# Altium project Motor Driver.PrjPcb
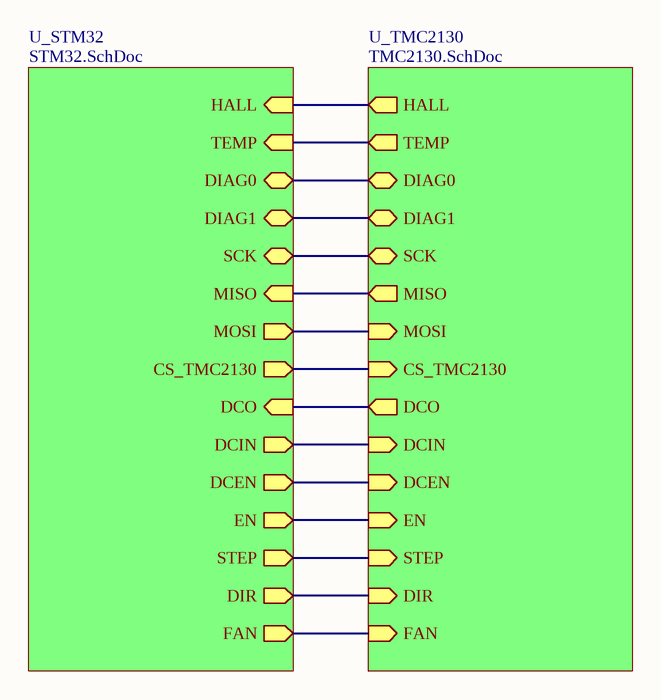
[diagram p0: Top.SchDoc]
3 sheets, 58 parts. Net scope: hierarchical (ports join the sheet entries above them; power ports are global).
Board file: PCB1.PcbDoc
Sheets:
  Top.SchDoc
    U_STM32 = STM32.SchDoc
    U_TMC2130 = TMC2130.SchDoc

## Sheet Top.SchDoc
size A

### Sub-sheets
U_STM32 = STM32.SchDoc: CS_TMC2130 (out), DIR (out), MISO (in), MOSI (out), SCK (bidir), EN (out), DIAG0 (bidir), HALL (in), DCO (in), DCEN (out), TEMP (in), DIAG1 (bidir), DCIN (out), STEP (out), FAN (out)
U_TMC2130 = TMC2130.SchDoc: DIAG1 (bidir), DIAG0 (bidir), DCO (out), DCIN (in), TEMP (out), HALL (out), DCEN (in), MOSI (in), SCK (bidir), MISO (out), STEP (in), DIR (in), EN (in), CS_TMC2130 (in), FAN (in)

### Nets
NetQ1_1: sheet U_STM32/FAN, sheet U_TMC2130/FAN
NetR2_2: sheet U_STM32/TEMP, sheet U_TMC2130/TEMP
NetU1_10: sheet U_STM32/CS_TMC2130, sheet U_TMC2130/CS_TMC2130
NetU1_11: sheet U_STM32/HALL, sheet U_TMC2130/HALL
NetU1_12: sheet U_STM32/EN, sheet U_TMC2130/EN
NetU1_13: sheet U_STM32/STEP, sheet U_TMC2130/STEP
NetU1_14: sheet U_STM32/DIR, sheet U_TMC2130/DIR
NetU1_15: sheet U_STM32/SCK, sheet U_TMC2130/SCK
NetU1_16: sheet U_STM32/MISO, sheet U_TMC2130/MISO
NetU1_17: sheet U_STM32/MOSI, sheet U_TMC2130/MOSI
NetU1_26: sheet U_STM32/DCO, sheet U_TMC2130/DCO
NetU1_27: sheet U_STM32/DCEN, sheet U_TMC2130/DCEN
NetU1_28: sheet U_STM32/DCIN, sheet U_TMC2130/DCIN
NetU1_45: sheet U_STM32/DIAG0, sheet U_TMC2130/DIAG0
NetU1_46: sheet U_STM32/DIAG1, sheet U_TMC2130/DIAG1

## Sheet STM32.SchDoc: Microcontroller & Communication
size A; Author: Luka & Emile; DrawnBy: Luka & Emile; Revision: 0.1; SheetNumber: 1; SheetTotal: 2
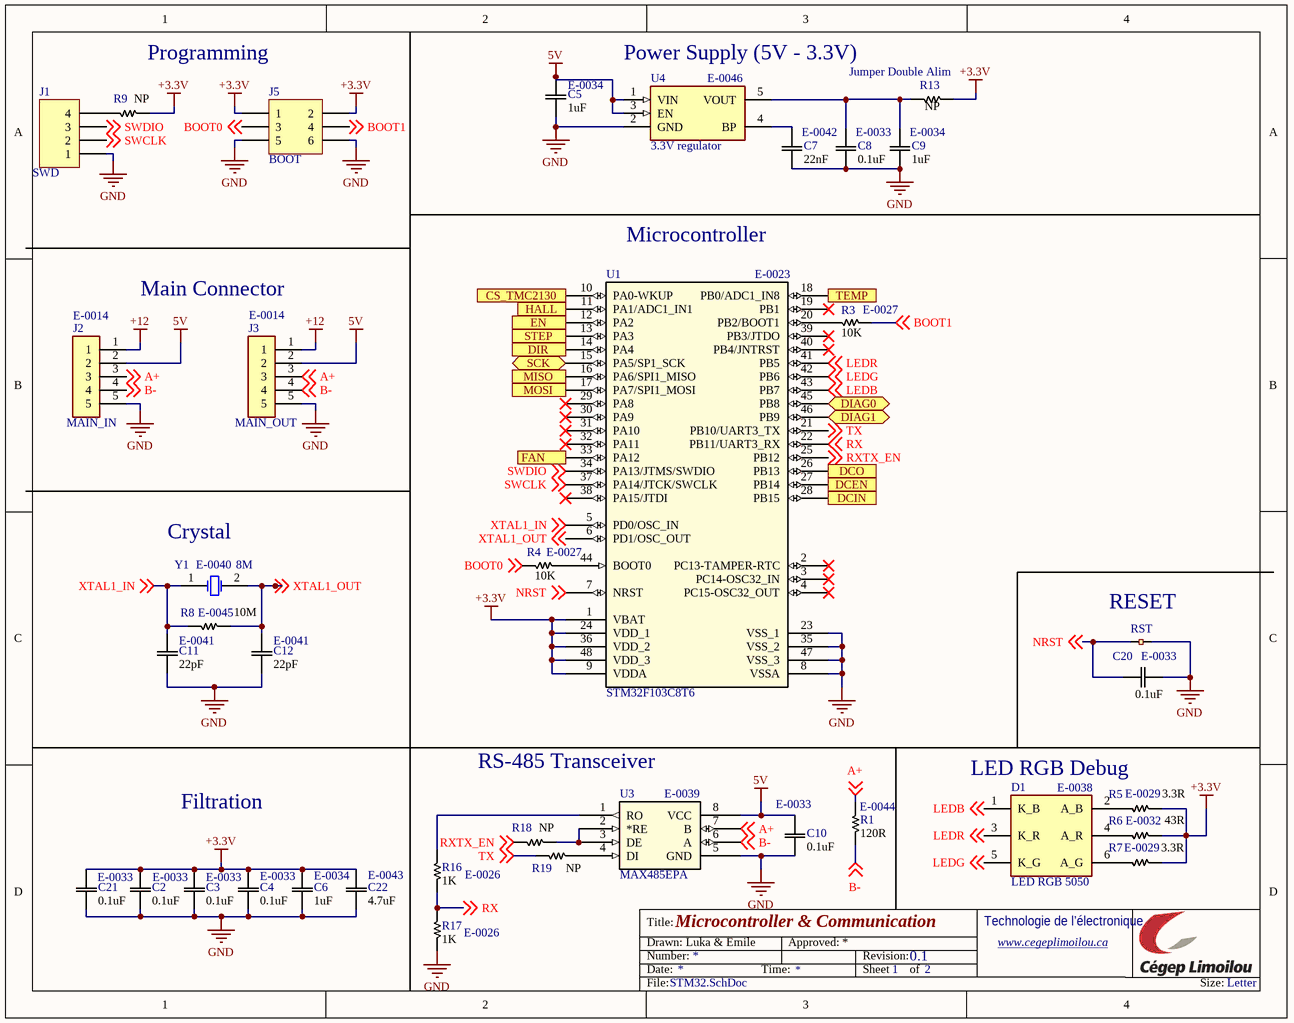
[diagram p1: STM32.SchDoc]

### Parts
C2  value 0.1uF  [0603]  (hidden comment: E-0033)
C3  value 0.1uF  [0603]  (hidden comment: E-0033)
C4  value 0.1uF  [0603]  (hidden comment: E-0033)
C5  value 1uF  [0603]  (hidden comment: E-0034)
C6  value 1uF  [0603]  (hidden comment: E-0034)
C7  value 22nF  [0603]  (hidden comment: E-0042)
C8  value 0.1uF  [0603]  (hidden comment: E-0033)
C9  value 1uF  [0603]  (hidden comment: E-0034)
C10  value 0.1uF  [0603]  (hidden comment: E-0033)
C11  value 22pF  [0603]  (hidden comment: E-0041)
C12  value 22pF  [0603]  (hidden comment: E-0041)
C20  value 0.1uF  [0603]  (hidden comment: E-0033)
C21  value 0.1uF  [0603]  (hidden comment: E-0033)
C22  value 4.7uF  [0603]  (hidden comment: E-0043)
D1  LED RGB 5050  [LED 5050]
J1  SWD  [HDR1X4]
J2  MAIN_IN  [JST 5POS 2.5mm 90°]
J3  MAIN_OUT  [JST 5POS 2.5mm 90°]
J5  BOOT  [Header 3x2 1.27mm SMD]
R1  value 120R  [0603]  (hidden comment: E-0044)
R3  value 10K  [0603]  (hidden comment: E-0027)
R4  value 10K  [0603]  (hidden comment: Resistor 0603)
R5  value 3.3R  [0603]  (hidden comment: E-0029)
R6  value 43R  [0603]  (hidden comment: E-0032)
R7  value 3.3R  [0603]  (hidden comment: E-0029)
R8  value 10M  [0603]  (hidden comment: E-0045)
R9  value NP  [0603]  (hidden comment: Jumper)
R13  value NP  [0603]  (hidden comment: Jumper)
R16  value 1K  [0603]  (hidden comment: E-0026)
R17  value 1K  [0603]  (hidden comment: E-0026)
R18  value NP  [0603]  (hidden comment: Jumper)
R19  value NP  [0603]  (hidden comment: Jumper)
RST  (no value)  [PAD]
U1  STM32F103C8T6  [LQFP-48]
U3  MAX485EPA  [DIP 8 - 3D]
U4  3.3V regulator  [SOT94P279X130-5N]
Y1  8M  [ATS080B-E]

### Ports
CS_TMC2130 (out), DCEN (out), DCIN (out), DCO (in), DIAG0 (bidir), DIAG1 (bidir), DIR (out), EN (out), FAN (out), HALL (in), MISO (in), MOSI (out), SCK (bidir), STEP (out), TEMP (in)

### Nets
5V: C5.2 C10.2 J2.2 J3.2 U3.8(VCC) U4.1(VIN) U4.3(EN)
+3.3V: C2.2 C3.2 C4.2 C6.2 C21.2 C22.2 J5.1 J5.2 R5.2 R6.2 R7.2 R9.2 R13.2 U1.1(VBAT) U1.9(VDDA) U1.24(VDD_1) U1.36(VDD_2) U1.48(VDD_3)
+12: J2.1 J3.1
GND: C2.1 C3.1 C4.1 C5.1 C6.1 C7.1 C8.1 C9.1 C10.1 C11.1 C12.1 C20.1 C21.1 C22.1 J1.1 J2.5 J3.5 J5.5 J5.6 R17.2 RST.1 U1.8(VSSA) U1.23(VSS_1) U1.35(VSS_2) U1.47(VSS_3) U3.5(GND) U4.2(GND)
A+: J2.3 J3.3 R1.2 U3.7(B) ; off-sheet A+
B-: J2.4 J3.4 R1.1 U3.6(A) ; off-sheet B-
BOOT0: J5.3 R4.1 ; off-sheet BOOT0
BOOT1: J5.4 R3.2 ; off-sheet BOOT1
LEDB: D1.1(K_B) U1.43(PB7) ; off-sheet LEDB
LEDG: D1.5(K_G) U1.42(PB6) ; off-sheet LEDG
LEDR: D1.3(K_R) U1.41(PB5) ; off-sheet LEDR
NRST: C20.2 RST.2 U1.7(NRST) ; off-sheet NRST
RX: R16.2 R17.1 U1.22(PB11/UART3_RX) ; off-sheet RX
RXTX_EN: R18.1 U1.25(PB12) ; off-sheet RXTX_EN
SWCLK: J1.2 U1.37(PA14/JTCK/SWCLK) ; off-sheet SWCLK
SWDIO: J1.3 U1.34(PA13/JTMS/SWDIO) ; off-sheet SWDIO
TX: R19.1 U1.21(PB10/UART3_TX) ; off-sheet TX
XTAL1_IN: C11.2 R8.1 U1.5(PD0/OSC_IN) Y1.1(OSC1) ; off-sheet XTAL1_IN
XTAL1_OUT: C12.2 R8.2 U1.6(PD1/OSC_OUT) Y1.2(OSC2) ; off-sheet XTAL1_OUT
NetC7_2: C7.2 U4.4(BP)
NetC8_2: C8.2 C9.2 R13.1 U4.5(VOUT)
NetD1_2: D1.2(A_B) R5.1
NetD1_4: D1.4(A_R) R6.1
NetD1_6: D1.6(A_G) R7.1
NetJ1_4: J1.4 R9.1
NetQ1_1: U1.33(PA12) ; port FAN
NetR2_2: U1.18(PB0/ADC1_IN8) ; port TEMP
NetR3_1: R3.1 U1.20(PB2/BOOT1)
NetR4_2: R4.2 U1.44(BOOT0)
NetR16_1: R16.1 U3.1(RO)
NetR18_2: R18.2 U3.2(*RE) U3.3(DE)
NetR19_2: R19.2 U3.4(DI)
NetU1_10: U1.10(PA0-WKUP) ; port CS_TMC2130
NetU1_11: U1.11(PA1/ADC1_IN1) ; port HALL
NetU1_12: U1.12(PA2) ; port EN
NetU1_13: U1.13(PA3) ; port STEP
NetU1_14: U1.14(PA4) ; port DIR
NetU1_15: U1.15(PA5/SP1_SCK) ; port SCK
NetU1_16: U1.16(PA6/SPI1_MISO) ; port MISO
NetU1_17: U1.17(PA7/SPI1_MOSI) ; port MOSI
NetU1_26: U1.26(PB13) ; port DCO
NetU1_27: U1.27(PB14) ; port DCEN
NetU1_28: U1.28(PB15) ; port DCIN
NetU1_45: U1.45(PB8) ; port DIAG0
NetU1_46: U1.46(PB9) ; port DIAG1

Not connected (* = marked no-connect by the designer): U1 2(PC13-TAMPER-RTC)* 3(PC14-OSC32_IN)* 4(PC15-OSC32_OUT)* 19(PB1)* 29(PA8)* 30(PA9)* 31(PA10)* 32(PA11)* 38(PA15/JTDI)* 39(PB3/JTDO)* 40(PB4/JNTRST)*

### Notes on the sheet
- Programming
- Power Supply (5V - 3.3V)
- (near R13) Jumper Double Alim
- Main Connector
- Microcontroller
- (near Y1) Crystal
- (near RST) RESET
- (near U3) RS-485 Transceiver
- LED RGB Debug
- Filtration

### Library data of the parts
C2-C4 C8 C10 C20 C21 = E-0033: 0.1uF Capacitor 0603 SMD; Manufacturer_Part_Number: C0603C104Z3VACTU; Manufacturer_Name: KEMET; Built_By: Luka & Émile
C5 C6 C9 = E-0034: 1uf Capacitor 0603 SMD; Manufacturer_Part_Number: CL10A105KA8NNNC; Manufacturer_Name: Samsung Electro-Mechanics; Built_By: Luka & Émile
C7 = E-0042: 22nF Capacitor 0603 SMD; Manufacturer_Part_Number: C0603C223K1RACTU; Manufacturer_Name: KEMET; Built_By: Luka & Émile
C11 C12 = E-0041: 22pF Capacitor 0603 SMD; Manufacturer_Part_Number: C0603C220J1GACTU; Manufacturer_Name: KEMET; Built_By: Luka & Émile
C22 = E-0043: 4.7uF Capacitor 0603 SMD; Manufacturer_Part_Number: C0603C475K9PACTU; Manufacturer_Name: KEMET; Built_By: Luka & Émile
D1 = E-0038: Manufacturer_Name: Wurth Elektronik; Manufacturer_Part_Number: 150505M173300; Built_By: Luka & Émile
J1 = E-0048: Header, 4POS; Manufacturer_Name: Würth Elektronik; Manufacturer_Part_Number: 61300411121; Built_By: Luka & Émile
J2 J3 = E-0014: Connector JST 5POS; Manufacturer_Name: JST Sales America Inc.; Manufacturer_Part_Number: S5B-XH-A-1(LF)(SN); Built_By: Luka & Émile
J5 = E-0049: Header, 3-Pin, Dual row; Manufacturer_Name: Sullins Connector Solutions; Manufacturer_Part_Number: GRPB032VWVN-RC; Built_By: Luka & Émile
R1 = E-0044: 120R Resistor 0603 SMD; Manufacturer_Part_Number: KDV06FR120ET; Manufacturer_Name: Ohmite; Built_By: Luka & Émile
R3 R4 = E-0027: 10K Resistor 0603 SMD; Manufacturer_Part_Number: RMCF0603JT10K0; Manufacturer_Name: Stackpole Electronics Inc; Built_By: Luka & Émile
R5 R7 = E-0029: 3.3R Resistor 0603 SMD; Manufacturer_Part_Number: MCR03ERTJ3R3; Manufacturer_Name: Rohm Semiconductor; Built_By: Luka & Émile
R6 = E-0032: 43R Resistor 0603 SMD; Manufacturer_Part_Number: RK73B1JTTD430J; Manufacturer_Name: KOA Speer Electronics, Inc.; Built_By: Luka & Émile
R8 = E-0045: 10M Resistor 0603 SMD; Manufacturer_Part_Number: CRCW060310M0FKEAC; Manufacturer_Name: Vishay Dale; Built_By: Luka & Émile
R9 R13 R18 R19 = Jumper: Jumper 0603; Built_By: Luka & Émile
R16 R17 = E-0026: 1K Resistor 0603 SMD; Manufacturer_Part_Number: RK73B1JTTD102J; Manufacturer_Name: KOA Speer Electronics, Inc.; Built_By: Luka & Émile
RST = PAD: SMD Pad for contact; Built_By: Luka & Émile
U1 = E-0023: STM32F103C8T6 Bluepill; Manufacturer_Part_Number: STM32F103C8T6TR; Manufacturer_Name: STMicroelectronics; Built_By: Luka & Émile
U3 = E-0039: RS485 Communication; Manufacturer_Part_Number: MAX485CPA+; Manufacturer_Name: Maxim Integrated; Built_By: Luka & Émile
U4 = E-0046: Voltage Regulator 3.3V SOT-23-5; Manufacturer_Name: Richtek USA Inc.; Manufacturer_Part_Number: RT9193-28GB; Built_By: Luka & Émile
Y1 = E-0040: Crystal 8M; Manufacturer_Name: CTS-Frequency Controls; Built_By: Luka & Émile

## Sheet TMC2130.SchDoc: Motor Driver & Sensors
size A; Author: Luka & Emile; DrawnBy: Luka & Emile; Revision: 0.1; SheetNumber: 2; SheetTotal: 2
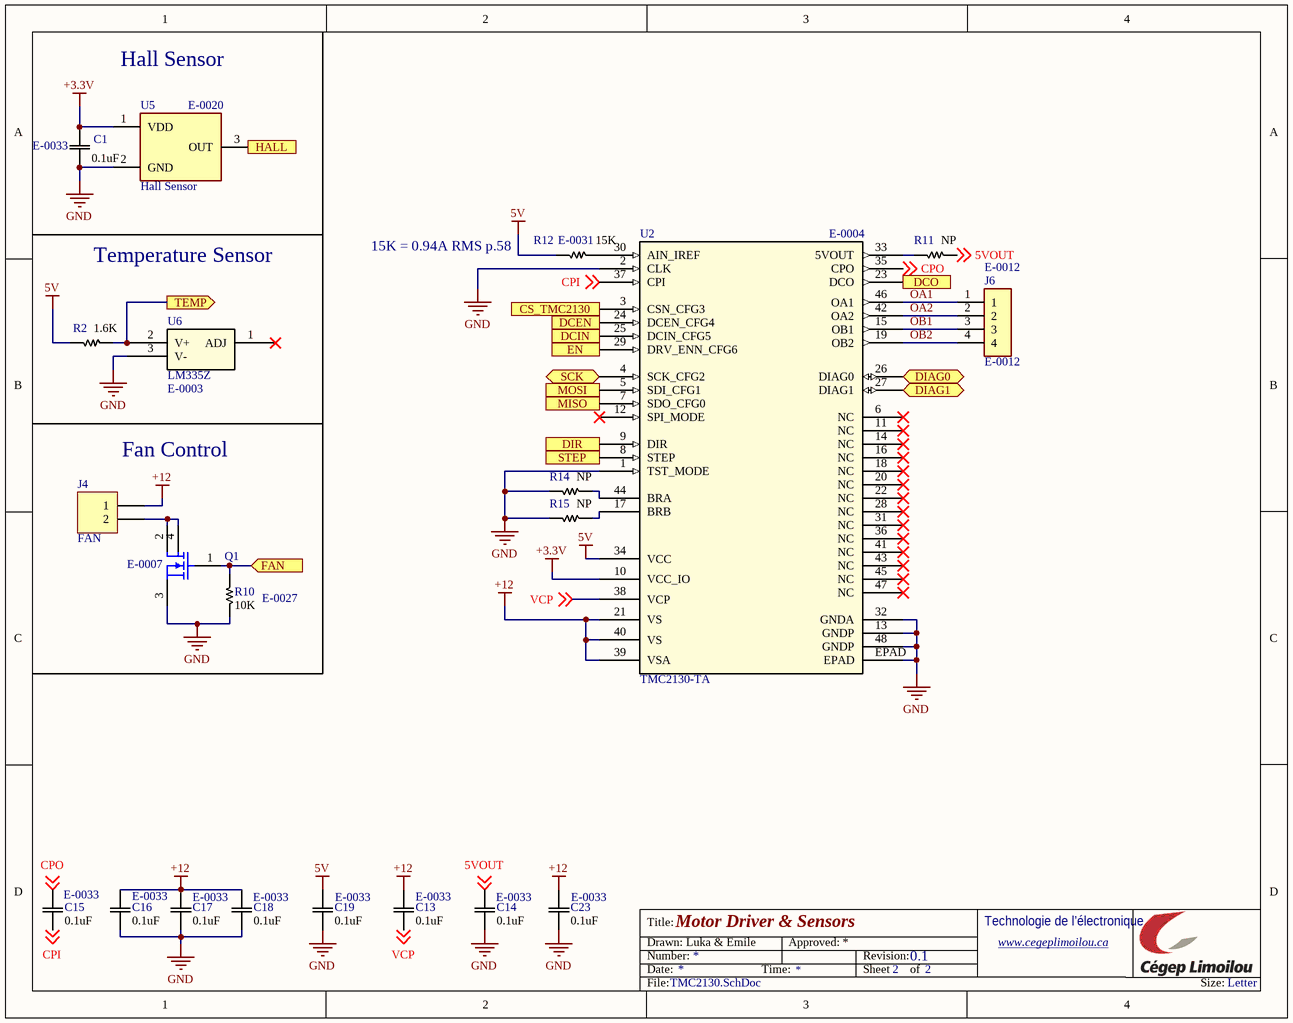
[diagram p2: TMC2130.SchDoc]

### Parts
C1  value 0.1uF  [0603]  (hidden comment: E-0033)
C13  value 0.1uF  [0603]  (hidden comment: E-0033)
C14  value 0.1uF  [0603]  (hidden comment: E-0033)
C15  value 0.1uF  [0603]  (hidden comment: E-0033)
C16  value 0.1uF  [0603]  (hidden comment: E-0033)
C17  value 0.1uF  [0603]  (hidden comment: E-0033)
C18  value 0.1uF  [0603]  (hidden comment: E-0033)
C19  value 0.1uF  [0603]  (hidden comment: E-0033)
C23  value 0.1uF  [0603]  (hidden comment: E-0033)
J4  FAN  [HDR1X2]
J6  E-0012  [JST 4POS 2.5mm 90°]
Q1  E-0007  [SOT223_M]
R2  value 1.6K  [0603]  (hidden comment: E-0050)
R10  value 10K  [0603]  (hidden comment: Resistor 0603)
R11  value NP  [0603]  (hidden comment: Jumper)
R12  value 15K  [0603]  (hidden comment: E-0031)
R14  value NP  [0603]  (hidden comment: Jumper)
R15  value NP  [0603]  (hidden comment: Jumper)
U2  TMC2130-TA  [eTQFP48_9x9]
U5  Hall Sensor  [AH372PB]
U6  LM335Z  [TO92]

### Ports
CS_TMC2130 (in), DCEN (in), DCIN (in), DCO (out), DIAG0 (bidir), DIAG1 (bidir), DIR (in), EN (in), FAN (in), HALL (out), MISO (out), MOSI (in), SCK (bidir), STEP (in), TEMP (out)

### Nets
5V: C19.2 R2.1 R12.1 U2.34(VCC)
+3.3V: C1.2 U2.10(VCC_IO) U5.1(VDD)
+12: C13.2 C16.2 C17.2 C18.2 C23.2 J4.1 U2.21(VS) U2.39(VSA) U2.40(VS)
GND: C1.1 C14.1 C16.1 C17.1 C18.1 C19.1 C23.1 Q1.3(S) R10.1 R14.1 R15.1 U2.1(TST_MODE) U2.2(CLK) U2.13(GNDP) U2.32(GNDA) U2.48(GNDP) U2.EPAD U5.2(GND) U6.3(V-)
5VOUT: C14.2 R11.2 ; off-sheet 5VOUT
CPI: C15.1 U2.37(CPI) ; off-sheet CPI
CPO: C15.2 U2.35(CPO) ; off-sheet CPO
OA1: J6.1 U2.46(OA1)
OA2: J6.2 U2.42(OA2)
OB1: J6.3 U2.15(OB1)
OB2: J6.4 U2.19(OB2)
VCP: C13.1 U2.38(VCP) ; off-sheet VCP
NetJ4_2: J4.2 Q1.2(D) Q1.4(D)
NetQ1_1: Q1.1(G) R10.2 ; port FAN
NetR2_2: R2.2 U6.2(V+) ; port TEMP
NetR11_1: R11.1 U2.33(5VOUT)
NetR12_2: R12.2 U2.30(AIN_IREF)
NetR14_2: R14.2 U2.44(BRA)
NetR15_2: R15.2 U2.17(BRB)
NetU1_10: U2.3(CSN_CFG3) ; port CS_TMC2130
NetU1_11: U5.3(OUT) ; port HALL
NetU1_12: U2.29(DRV_ENN_CFG6) ; port EN
NetU1_13: U2.8(STEP) ; port STEP
NetU1_14: U2.9(DIR) ; port DIR
NetU1_15: U2.4(SCK_CFG2) ; port SCK
NetU1_16: U2.7(SDO_CFG0) ; port MISO
NetU1_17: U2.5(SDI_CFG1) ; port MOSI
NetU1_26: U2.23(DCO) ; port DCO
NetU1_27: U2.24(DCEN_CFG4) ; port DCEN
NetU1_28: U2.25(DCIN_CFG5) ; port DCIN
NetU1_45: U2.26(DIAG0) ; port DIAG0
NetU1_46: U2.27(DIAG1) ; port DIAG1

Not connected (* = marked no-connect by the designer): U2 6(NC)* 11(NC)* 12(SPI_MODE)* 14(NC)* 16(NC)* 18(NC)* 20(NC)* 22(NC)* 28(NC)* 31(NC)* 36(NC)* 41(NC)* 43(NC)* 45(NC)* 47(NC)*; U6 1(ADJ)*

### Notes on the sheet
- Hall Sensor
- Temperature Sensor
- (near R12) 15K = 0.94A RMS p.58
- (near J4) Fan Control

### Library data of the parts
C1 C13-C19 C23 = E-0033: as C2 on sheet STM32
J4 = E-0047: Header, 2-Pin; Manufacturer_Name: Würth Elektronik; Manufacturer_Part_Number: 61300411121; Built_By: Luka & Émile
J6 = E-0012: Connector JST 4POS; Manufacturer_Name: JST Sales America Inc.; Manufacturer_Part_Number: S4B-XH-A(LF)(SN); Built_By: Luka & Émile
Q1 = E-0007: 55V 7A SOT223; Manufacturer_Name: Nexperia USA Inc.; Manufacturer_Part_Number: BUK9880-55A/CUX; Built_By: Luka & Émile
R2 = E-0050: 1.6K Resistor 0603 SMD; Manufacturer_Part_Number: CRCW06031K60JNEA; Manufacturer_Name: Vishay Dale; Built_By: Luka & Émile
R10 = E-0027: as R3 on sheet STM32
R11 R14 R15 = Jumper: Jumper 0603; Built_By: Luka & Émile
R12 = E-0031: 15K Resistor 0603 SMD; Manufacturer_Part_Number: RMCF0603FG15K0; Manufacturer_Name: Stackpole Electronics Inc; Built_By: Luka & Émile
U2 = E-0004: Motor Driver TMC2130-TA; Manufacturer_Part_Number: TMC2130-TA-T; Manufacturer_Name: Trinamic Motion Control GmbH; Built_By: Luka & Émile
U5 = E-0020: Manufacturer_Name: Diodes Incorporated; Manufacturer_Part_Number: AH372-P-B; Built_By: Luka & Émile
U6 = E-0003: Temperature Sensor LM335Z; Manufacturer_Name: STMicroelectronics; Built_By: Luka & Émile

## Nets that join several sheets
5V: STM32 (7 pins), TMC2130 (C19.2 R2.1 R12.1 U2.34)
+3.3V: STM32 (18 pins), TMC2130 (C1.2 U2.10 U5.1)
+12: STM32 (J2.1 J3.1), TMC2130 (9 pins)
GND: STM32 (27 pins), TMC2130 (19 pins)
NetQ1_1: STM32 (U1.33), TMC2130 (Q1.1 R10.2)
NetR2_2: STM32 (U1.18), TMC2130 (R2.2 U6.2)
NetU1_10: STM32 (U1.10), TMC2130 (U2.3)
NetU1_11: STM32 (U1.11), TMC2130 (U5.3)
NetU1_12: STM32 (U1.12), TMC2130 (U2.29)
NetU1_13: STM32 (U1.13), TMC2130 (U2.8)
NetU1_14: STM32 (U1.14), TMC2130 (U2.9)
NetU1_15: STM32 (U1.15), TMC2130 (U2.4)
NetU1_16: STM32 (U1.16), TMC2130 (U2.7)
NetU1_17: STM32 (U1.17), TMC2130 (U2.5)
NetU1_26: STM32 (U1.26), TMC2130 (U2.23)
NetU1_27: STM32 (U1.27), TMC2130 (U2.24)
NetU1_28: STM32 (U1.28), TMC2130 (U2.25)
NetU1_45: STM32 (U1.45), TMC2130 (U2.26)
NetU1_46: STM32 (U1.46), TMC2130 (U2.27)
